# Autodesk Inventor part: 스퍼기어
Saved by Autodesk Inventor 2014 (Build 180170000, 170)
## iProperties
Created: 2026-09
Part Number: 스퍼기어
Material: 일반
Document SubType Name: Modeling
Designer: dg
Density: 1 g/cm^3
Appearance: 기본값
Author: dg
Author: jhkim
Creation Date: 2026-08-26
Sending System: Autodesk Inventor 2027
Preprocessor: ST-DEVELOPER v20.1
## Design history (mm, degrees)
node "스퍼기어1"
node "솔리드1"
node "기준1"
